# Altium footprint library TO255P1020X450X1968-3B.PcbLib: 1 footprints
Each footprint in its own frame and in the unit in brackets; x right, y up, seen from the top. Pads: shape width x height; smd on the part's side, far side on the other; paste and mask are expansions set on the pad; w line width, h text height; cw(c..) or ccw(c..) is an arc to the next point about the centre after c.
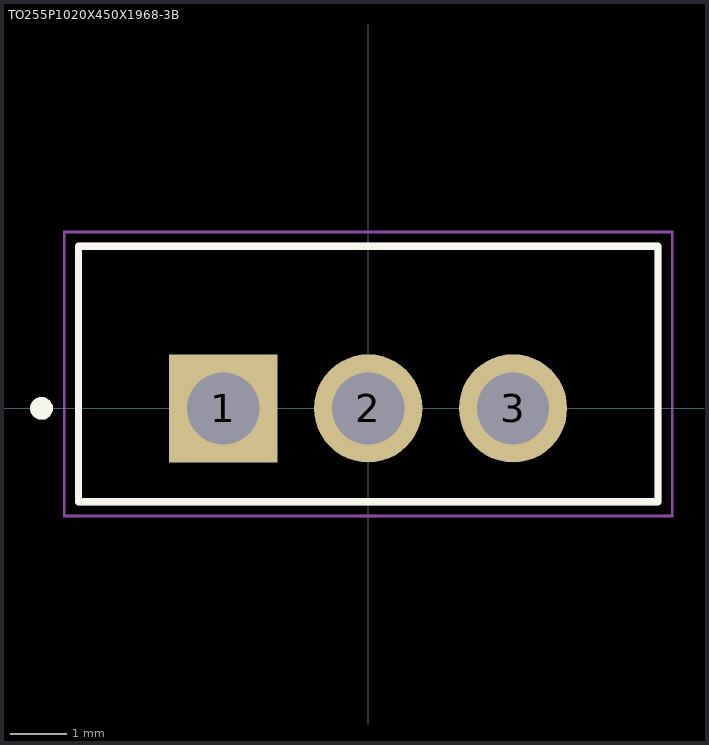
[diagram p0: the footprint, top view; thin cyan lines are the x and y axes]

## TO255P1020X450X1968-3B [mm]
height 19.68
pads (3):
  rect 1.905x1.905 / inner round 1.905 / far side rect 1.905x1.905 hole 1.27: 1(-2.55,0)
  round 1.905 hole 1.27: 2(0,0) 3(2.55,0)
Top Overlay:
  circle w0.2: c-5.75,0 r0.1
  lines w0.127: -5.1,-1.645 -5.1,2.855 5.1,2.855 5.1,-1.645 -5.1,-1.645
Mechanical 13:
  circle w0.2: c-5.75,0 r0.1
  lines w0.127: -5.1,-1.645 -5.1,2.855 5.1,2.855 5.1,-1.645 -5.1,-1.645
Mechanical 15:
  lines w0.05: -5.35,-1.895 5.35,-1.895 5.35,3.105 -5.35,3.105 -5.35,-1.895
3D body "step_temp.STEP": height 19.68, standoff -9.22, extent -5.1,-2.25 5.1,2.25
